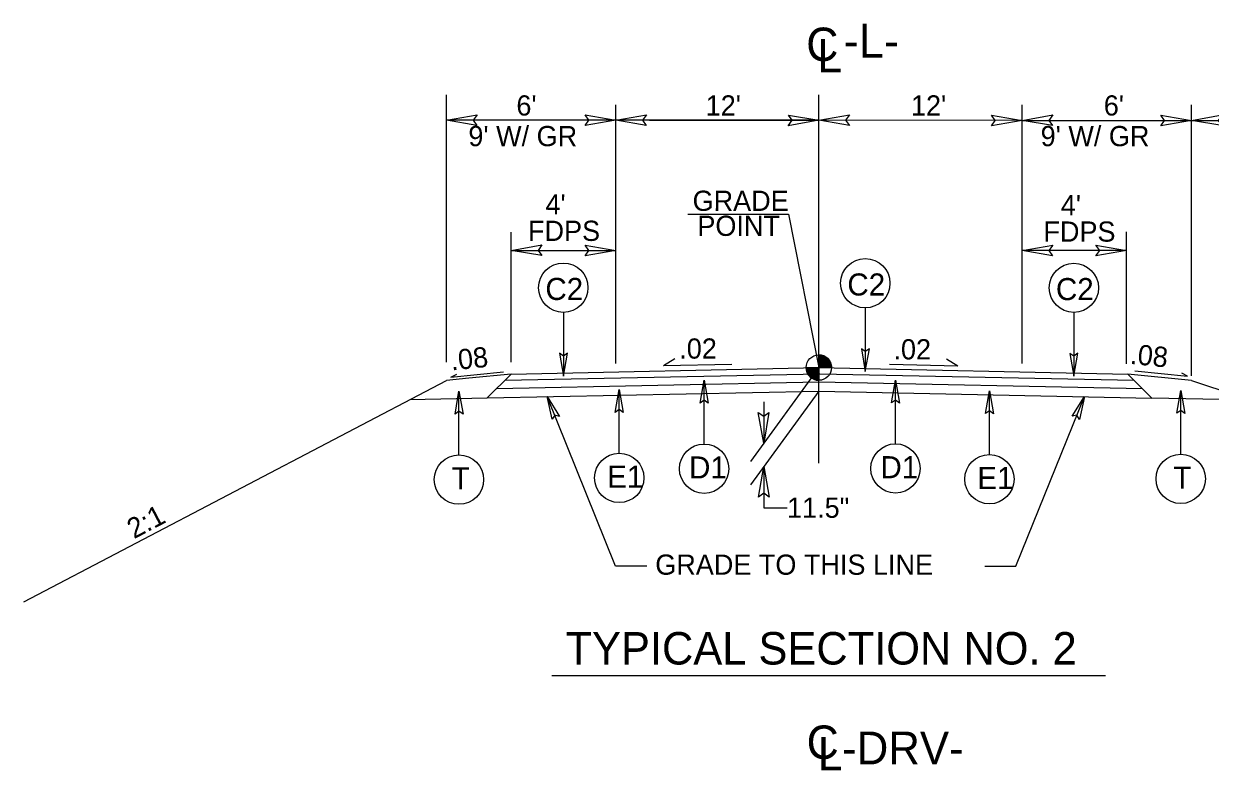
# Model space of a CAD drawing. Extents: x 1718167 to 1721223, y 797898 to 799800.
# Drawn here: x 1719533.1 to 1719953.6, y 798561.1 to 798825.7 of the extents above; entities that cross this region are included whole.
import ezdxf

# ---------------------------------------------------------------- set-up
doc = ezdxf.new("R2010")
doc.units = 0
for name, color, linetype in [('Old_Level_1', 7, 'Continuous'), ('Old_Level_2', 7, 'Continuous'), ('Prop Dimension Text', 7, 'Continuous'), ('Prop Terminator CELL', 7, 'Continuous'), ('Typical ID Circle CELL', 7, 'Continuous'), ('Typical Slope Point Local CELL', 7, 'Continuous'), ('Typical Terminator CELL', 7, 'Continuous'), ('Typical Text Centerline CELL', 7, 'Continuous'), ('Typical Text Grade Point CELL', 7, 'Continuous'), ('Typical Text ID Circle CELL', 7, 'Continuous'), ('Typical Text Label CELL', 7, 'Continuous')]:
    doc.layers.add(name, color=color, linetype=linetype)

# ---------------------------------------------------------------- blocks, each defined once
blk = doc.blocks.new('TERMINATOR')
at = {"layer": 'Typical Terminator CELL'}
blk.add_lwpolyline([(-0.469, 0.081), (0, 0), (-0.471, -0.083), (-0.411, 0)], close=True, dxfattribs=at)

msp = doc.modelspace()

# ---------------------------------------------------------------- linework, layer by layer
at = {"layer": 'Old_Level_1'}
for p, q in [((1719682.9, 798705.72), (1719682.92, 798800.44)), ((1719742.9, 798705.23), (1719742.92, 798796.97)), ((1719886.9, 798705.2), (1719886.92, 798796.94)), ((1719946.9, 798700.93), (1719946.92, 798796.93)), ((1719742.92, 798791.45), (1719682.92, 798791.47)), ((1719814.92, 798791.44), (1719742.92, 798791.45)), ((1719754.92, 798791.45), (1719814.92, 798791.44)), ((1719886.92, 798791.42), (1719814.92, 798791.44)), ((1719886.92, 798791.42), (1719946.92, 798791.41)), ((1719946.92, 798791.41), (1720018.92, 798791.4)), ((1719768.42, 798758.2), (1719804.11, 798758.19)), ((1719804.11, 798758.19), (1719814.9, 798703.8)), ((1719705.9, 798705.71), (1719705.91, 798751.74)), ((1719923.9, 798705.19), (1719923.91, 798751.86)), ((1719705.9, 798745.33), (1719742.9, 798745.33)), ((1719923.91, 798745.32), (1719886.91, 798745.33)), ((1719814.9, 798703.8), (1719814.9, 798708.3)), ((1719814.9, 798703.8), (1719790.62, 798670.56)), ((1719810.4, 798703.8), (1719814.9, 798703.8)), ((1719814.89, 798699.3), (1719814.9, 798703.8)), ((1719814.9, 798703.8), (1719814.89, 798699.3)), ((1719819.4, 798703.8), (1719814.9, 798703.8)), ((1719690.81, 798700.01), (1719682.9, 798699.21)), ((1719705.9, 798701.53), (1719690.81, 798700.01)), ((1719946.98, 798699.23), (1719924.43, 798701.52)), ((1719926.87, 798702.66), (1719945.59, 798700.76)), ((1719945.59, 798700.76), (1719943.51, 798701.8)), ((1719814.9, 798695.48), (1719790.62, 798662.24)), ((1719946.98, 798699.23), (1720018.96, 798675.22)), ((1719742.88, 798633.46), (1719718.63, 798693.52)), ((1719795.37, 798691.71), (1719795.37, 798677.06)), ((1719884.74, 798633.46), (1719908.99, 798693.52)), ((1719795.37, 798668.75), (1719795.37, 798654.16)), ((1719795.37, 798654.16), (1719803.64, 798654.16)), ((1719753.93, 798633.46), (1719742.88, 798633.46)), ((1719873.69, 798633.46), (1719884.74, 798633.46))]:
    msp.add_line(p, q, dxfattribs=at)
for points in [[(1719814.94, 798708.3), (1719814.94, 798708.3), (1719814.94, 798703.8)], [(1719815.03, 798708.3), (1719815.03, 798703.8)], [(1719815.12, 798708.29), (1719815.12, 798703.8)], [(1719815.21, 798708.29), (1719815.21, 798703.8)], [(1719815.3, 798708.28), (1719815.3, 798703.8)], [(1719815.39, 798708.27), (1719815.39, 798703.8)], [(1719815.48, 798708.26), (1719815.48, 798703.8)], [(1719815.57, 798708.25), (1719815.57, 798703.8)], [(1719815.66, 798708.24), (1719815.66, 798703.8)], [(1719815.75, 798708.22), (1719815.75, 798703.8)], [(1719815.84, 798708.2), (1719815.84, 798703.8)], [(1719815.93, 798708.18), (1719815.93, 798703.8)], [(1719816.02, 798708.16), (1719816.02, 798703.8)], [(1719816.11, 798708.13), (1719816.11, 798703.8)], [(1719816.2, 798708.11), (1719816.2, 798703.8)], [(1719816.29, 798708.08), (1719816.29, 798703.8)], [(1719816.38, 798708.05), (1719816.38, 798703.8)], [(1719816.47, 798708.02), (1719816.47, 798703.8)], [(1719816.56, 798707.98), (1719816.56, 798703.8)], [(1719816.65, 798707.94), (1719816.65, 798703.8)], [(1719816.74, 798707.9), (1719816.74, 798703.8)], [(1719816.83, 798707.86), (1719816.83, 798703.8)], [(1719816.92, 798707.82), (1719816.92, 798703.8)], [(1719817.01, 798707.77), (1719817.01, 798703.8)], [(1719817.1, 798707.72), (1719817.1, 798703.8)], [(1719817.19, 798707.67), (1719817.19, 798703.8)], [(1719810.42, 798703.8), (1719810.42, 798703.31)], [(1719810.51, 798703.8), (1719810.51, 798702.78)], [(1719810.6, 798703.8), (1719810.6, 798702.46)], [(1719810.69, 798703.8), (1719810.69, 798702.19)], [(1719810.78, 798703.8), (1719810.78, 798701.98)], [(1719810.87, 798703.8), (1719810.87, 798701.79)], [(1719810.96, 798703.8), (1719810.96, 798701.62)], [(1719811.05, 798703.8), (1719811.05, 798701.46)], [(1719811.14, 798703.8), (1719811.14, 798701.32)], [(1719811.23, 798703.8), (1719811.23, 798701.19)], [(1719811.32, 798703.8), (1719811.32, 798701.07)], [(1719811.41, 798703.8), (1719811.41, 798700.96)], [(1719811.5, 798703.8), (1719811.5, 798700.85)], [(1719811.59, 798703.8), (1719811.59, 798700.75)], [(1719811.68, 798703.8), (1719811.68, 798700.65)], [(1719811.77, 798703.8), (1719811.77, 798700.56)], [(1719811.86, 798703.8), (1719811.86, 798700.48)], [(1719811.95, 798703.8), (1719811.95, 798700.4)], [(1719812.04, 798703.8), (1719812.04, 798700.32)], [(1719812.13, 798703.8), (1719812.13, 798700.25)], [(1719812.22, 798703.8), (1719812.22, 798700.18)], [(1719812.31, 798703.8), (1719812.31, 798700.12)], [(1719812.4, 798703.8), (1719812.4, 798700.06)], [(1719812.49, 798703.8), (1719812.49, 798700)], [(1719812.58, 798703.8), (1719812.58, 798699.94)], [(1719812.67, 798703.8), (1719812.67, 798699.89)], [(1719812.76, 798703.8), (1719812.76, 798699.84)], [(1719812.85, 798703.8), (1719812.85, 798699.79)], [(1719812.94, 798703.8), (1719812.94, 798699.75)], [(1719813.03, 798703.8), (1719813.03, 798699.71)], [(1719813.12, 798703.8), (1719813.12, 798699.67)], [(1719813.21, 798703.8), (1719813.21, 798699.63)], [(1719813.3, 798703.8), (1719813.3, 798699.59)], [(1719813.39, 798703.8), (1719813.39, 798699.56)], [(1719813.48, 798703.8), (1719813.48, 798699.53)], [(1719813.57, 798703.8), (1719813.57, 798699.5)], [(1719813.66, 798703.8), (1719813.66, 798699.48)], [(1719813.75, 798703.8), (1719813.75, 798699.45)], [(1719813.84, 798703.8), (1719813.84, 798699.43)], [(1719813.93, 798703.8), (1719813.93, 798699.41)], [(1719814.02, 798703.8), (1719814.02, 798699.39)], [(1719814.11, 798703.8), (1719814.11, 798699.37)], [(1719814.2, 798703.8), (1719814.2, 798699.36)], [(1719814.29, 798703.8), (1719814.29, 798699.34)], [(1719814.38, 798703.8), (1719814.38, 798699.33)], [(1719814.47, 798703.8), (1719814.47, 798699.32)], [(1719814.56, 798703.8), (1719814.56, 798699.31)], [(1719814.65, 798703.8), (1719814.65, 798699.31)], [(1719814.74, 798703.8), (1719814.74, 798699.3)], [(1719814.83, 798703.8), (1719814.83, 798699.3), (1719814.83, 798699.3)], [(1719817.28, 798707.62), (1719817.28, 798703.8)], [(1719817.37, 798707.56), (1719817.37, 798703.8)], [(1719817.46, 798707.5), (1719817.46, 798703.8)], [(1719817.55, 798707.43), (1719817.55, 798703.8)], [(1719817.64, 798707.37), (1719817.64, 798703.8)], [(1719817.73, 798707.3), (1719817.73, 798703.8)], [(1719817.82, 798707.22), (1719817.82, 798703.8)], [(1719817.91, 798707.14), (1719817.91, 798703.8)], [(1719818, 798707.06), (1719818, 798703.8)], [(1719818.09, 798706.97), (1719818.09, 798703.8)], [(1719818.18, 798706.88), (1719818.18, 798703.8)], [(1719818.27, 798706.78), (1719818.27, 798703.8)], [(1719818.36, 798706.67), (1719818.36, 798703.8)], [(1719818.45, 798706.56), (1719818.45, 798703.8)], [(1719818.54, 798706.44), (1719818.54, 798703.8)], [(1719818.63, 798706.31), (1719818.63, 798703.8)], [(1719818.72, 798706.17), (1719818.72, 798703.8)], [(1719818.81, 798706.02), (1719818.81, 798703.8)], [(1719818.9, 798705.86), (1719818.9, 798703.8)], [(1719818.99, 798705.67), (1719818.99, 798703.8)], [(1719819.08, 798705.46), (1719819.08, 798703.8)], [(1719819.17, 798705.21), (1719819.17, 798703.8)], [(1719819.26, 798704.9), (1719819.26, 798703.8)], [(1719819.35, 798704.44), (1719819.35, 798703.8)]]:
    msp.add_lwpolyline(points, dxfattribs=at)
msp.add_circle((1719814.89, 798703.8), 4.5, dxfattribs=at)
for start, end in [(359.9785, 89.9785), (179.9785, 269.9785)]:
    msp.add_arc((1719814.89, 798703.8), 4.5, start, end, dxfattribs=at)
at = {"layer": 'Old_Level_2'}
for p, q in [((1719759.82, 798704.56), (1719763.9, 798707.03)), ((1719759.82, 798704.56), (1719784.11, 798705.05)), ((1719864.2, 798704.36), (1719839.92, 798704.85)), ((1719864.2, 798704.36), (1719860.12, 798706.82)), ((1719684.48, 798700.46), (1719703.2, 798702.34)), ((1719684.48, 798700.46), (1719686.56, 798701.5))]:
    msp.add_line(p, q, dxfattribs=at)
at = {"layer": 'Prop Terminator CELL'}
for points in [[(1719693.72, 798789.6), (1719682.92, 798791.47), (1719693.78, 798793.38), (1719692.4, 798791.46)], [(1719732.12, 798793.32), (1719742.92, 798791.45), (1719732.06, 798789.54), (1719733.44, 798791.46)], [(1719753.72, 798789.59), (1719742.92, 798791.45), (1719753.78, 798793.37), (1719752.4, 798791.45)], [(1719804.12, 798793.3), (1719814.92, 798791.44), (1719804.06, 798789.52), (1719805.44, 798791.44)], [(1719825.72, 798789.58), (1719814.92, 798791.44), (1719825.78, 798793.36), (1719824.4, 798791.44)], [(1719876.12, 798793.29), (1719886.92, 798791.42), (1719876.06, 798789.51), (1719877.44, 798791.42)], [(1719897.72, 798789.56), (1719886.92, 798791.42), (1719897.78, 798793.34), (1719896.4, 798791.42)], [(1719936.12, 798793.27), (1719946.92, 798791.41), (1719936.06, 798789.49), (1719937.44, 798791.41)], [(1719957.72, 798789.55), (1719946.92, 798791.41), (1719957.78, 798793.33), (1719956.4, 798791.41)], [(1719716.7, 798743.47), (1719705.9, 798745.33), (1719716.76, 798747.25), (1719715.38, 798745.33)], [(1719732.1, 798747.19), (1719742.9, 798745.33), (1719732.04, 798743.41), (1719733.42, 798745.33)], [(1719897.71, 798743.46), (1719886.91, 798745.33), (1719897.77, 798747.24), (1719896.39, 798745.32)], [(1719913.11, 798747.18), (1719923.91, 798745.32), (1719913.05, 798743.4), (1719914.43, 798745.32)], [(1719797.22, 798687.86), (1719795.37, 798677.06), (1719793.44, 798687.92), (1719795.37, 798686.54)], [(1719793.53, 798657.94), (1719795.37, 798668.75), (1719797.31, 798657.89), (1719795.38, 798659.27)]]:
    msp.add_lwpolyline(points, close=True, dxfattribs=at)
at = {"layer": 'Typical ID Circle CELL'}
for p, q in [((1719831.36, 798724.96), (1719831.36, 798702.36)), ((1719724.36, 798723.38), (1719724.36, 798700.78)), ((1719905.27, 798723.33), (1719905.27, 798700.73)), ((1719774.25, 798676.71), (1719774.25, 798699.31)), ((1719842.06, 798676.79), (1719842.06, 798699.39)), ((1719687.37, 798672.83), (1719687.37, 798695.42)), ((1719744.17, 798673.45), (1719744.17, 798696.04)), ((1719875.34, 798672.99), (1719875.34, 798695.58)), ((1719943.13, 798673.12), (1719943.13, 798695.71))]:
    msp.add_line(p, q, dxfattribs=at)
for centre in [(1719831.36, 798733.7), (1719724.35, 798732.12), (1719905.27, 798732.07), (1719774.25, 798667.97), (1719842.06, 798668.05), (1719687.37, 798664.09), (1719744.17, 798664.71), (1719875.34, 798664.25), (1719943.13, 798664.37)]:
    msp.add_circle(centre, 8.74, dxfattribs=at)
at = {"layer": 'Typical Slope Point Local CELL'}
for p, q in [((1719705.9, 798701.53), (1719814.9, 798703.8)), ((1719814.9, 798703.8), (1719924.43, 798701.52)), ((1719705.9, 798701.53), (1719697.41, 798693.03)), ((1719703.66, 798699.29), (1719815.19, 798701.61)), ((1719815.19, 798701.61), (1719926.66, 798699.29)), ((1719924.43, 798701.52), (1719932.93, 798693.02)), ((1719533.13, 798620.77), (1719682.9, 798699.21)), ((1719697.41, 798693.03), (1719814.9, 798695.48)), ((1719700.8, 798696.42), (1719814.9, 798698.8)), ((1719814.9, 798698.8), (1719929.54, 798696.41)), ((1719814.9, 798695.48), (1719932.93, 798693.02)), ((1719670.01, 798692.46), (1719697.41, 798693.03)), ((1719967.76, 798692.3), (1719932.93, 798693.02))]:
    msp.add_line(p, q, dxfattribs=at)
at = {"layer": 'Typical Text Centerline CELL'}
msp.add_line((1719814.89, 798669.95), (1719814.92, 798800.48), dxfattribs=at)
at = {"layer": 'Typical Text Label CELL'}
msp.add_line((1719720.25, 798594.7), (1719916.53, 798594.7), dxfattribs=at)

# ---------------------------------------------------------------- block references
at = {"layer": 'Typical Terminator CELL', "xscale": 17.2740059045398}
for p, yscale, rotation in [((1719724.36, 798700.78), -17.2740059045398, -90), ((1719831.36, 798702.36), -17.2740059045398, -90), ((1719905.27, 798700.73), -17.2740059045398, -90), ((1719774.25, 798699.31), 17.2740059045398, 90), ((1719842.06, 798699.39), 17.2740059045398, 90), ((1719687.37, 798695.42), 17.2740059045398, 90), ((1719744.17, 798696.04), 17.2740059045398, 90), ((1719875.34, 798695.58), 17.2740059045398, 90), ((1719943.13, 798695.71), 17.2740059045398, 90), ((1719718.63, 798693.52), 17.2740059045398, 111.98724998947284), ((1719908.99, 798693.52), 17.2740059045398, 68.01275001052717)]:
    msp.add_blockref('TERMINATOR', p, dxfattribs=dict(at, yscale=yscale, rotation=rotation))

# ---------------------------------------------------------------- texts
at = {"layer": 'Old_Level_1'}
for s, height, rotation, p in [("6'", 7.161, 359.988, (1719707.72, 798793.13)), ("12'", 7.161, 359.988, (1719774.8, 798793.13)), ("12'", 7.161, 359.988, (1719847.55, 798793.13)), ("6'", 7.161, 359.988, (1719915.87, 798793.13)), ("9' W/ GR", 7.161, 359.988, (1719690.71, 798782.27)), ("9' W/ GR", 7.161, 359.988, (1719893.5, 798782.27)), (" 4' ", 7.161, 359.988, (1719715.36, 798758.09)), (" 4' ", 7.161, 359.9878, (1719897.99, 798757.81)), ('FDPS', 7.161, 359.988, (1719711.84, 798748.7)), ('FDPS', 7.161, 359.9878, (1719894.48, 798748.43)), ('11.5"', 7.161, 359.988, (1719803.64, 798650.58)), ('GRADE TO THIS LINE', 7.1614, 359.988, (1719756.93, 798630.4))]:
    msp.add_text(s, height=height, rotation=rotation, dxfattribs=at).set_placement(p)
at = {"layer": 'Old_Level_2'}
for rotation, p in [(354.2008, (1719924.98, 798705.16)), (5.7484, (1719684.74, 798702.78))]:
    msp.add_text('.08 ', height=7.161, rotation=rotation, dxfattribs=at).set_placement(p)
at = {"layer": 'Prop Dimension Text'}
for s, p in [('GRADE', (1719770.16, 798759.34)), ('POINT', (1719771.85, 798750.48)), ('.02', (1719765.44, 798706.98)), ('.02', (1719841.34, 798706.71))]:
    msp.add_text(s, height=7.161, rotation=359.988, dxfattribs=at).set_placement(p)
at = {"layer": 'Typical Slope Point Local CELL'}
msp.add_text('2:1', height=7.161, rotation=27.6461, dxfattribs=at).set_placement((1719572.18, 798642.95))
at = {"layer": 'Typical Text Centerline CELL'}
for p in [(1719810.42, 798812.46), (1719810.56, 798565.14)]:
    msp.add_text('C', height=11.82, dxfattribs=at).set_placement(p)
for p in [(1719814.35, 798808.43), (1719814.49, 798561.11)]:
    msp.add_text('L', height=11.82, rotation=359.9469, dxfattribs=at).set_placement(p)
at = {"layer": 'Typical Text Grade Point CELL'}
msp.add_text('-L-', height=12, dxfattribs=at).set_placement((1719823.72, 798813.66))
at = {"layer": 'Typical Text ID Circle CELL'}
for s, height, p in [('C2', 7.826, (1719825.01, 798729.34)), ('C2', 7.826, (1719718, 798727.76)), ('C2', 7.826, (1719898.92, 798727.71)), ('D1', 7.826, (1719768.91, 798664.51)), ('D1', 7.826, (1719836.72, 798664.59)), ('T', 7.83, (1719684.75, 798660.62)), ('E1', 7.826, (1719739.89, 798661.24)), ('E1', 7.826, (1719871.06, 798660.78)), ('T', 7.83, (1719940.51, 798660.91))]:
    msp.add_text(s, height=height, dxfattribs=at).set_placement(p)
at = {"layer": 'Typical Text Label CELL'}
for s, height, p in [('TYPICAL SECTION NO. 2', 11.5, (1719725.13, 798598.58)), ('-DRV-', 11.601, (1719823.14, 798563.2))]:
    msp.add_text(s, height=height, dxfattribs=at).set_placement(p)

doc.saveas('drawing.dxf')
